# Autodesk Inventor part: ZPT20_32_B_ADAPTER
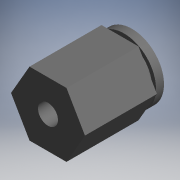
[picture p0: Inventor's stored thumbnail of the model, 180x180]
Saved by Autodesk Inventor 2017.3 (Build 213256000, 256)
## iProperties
Part Number: ZPT20_32_B_ADAPTER
Material: Generic
Catalog Web Link: www.cadenas.de
Description: ZPT_20_32B_ADEPTER-Vacuum Pad/Vertical Vacuum Entry With Buffer
Vendor: SMC
Document SubType Name: Modeling
Designer: partserver
Manufacturer: SMC
Mass: 0.516797 g
Surface Area: 4.92606 cm^2
Volume: 0.516797 cm^3
Density: 1 g/cm^3
Appearance: PSOLRGB-128-128-128
Category: PARTsolutions
Company: SMC
Title: ZPT20_32_B_ADAPTER
Author: Cadenas PARTsolutions
Comments: Vacuum Pad/Vertical Vacuum Entry With Buffer
PSOL_IDENT_0: {$CADENAS_DATA\23d-libs\smc_jp\vacuum_equipment\vacuum_pad\zp\zpt_b\zpt_20_32_b\parts\zpt_20_32_adap
PSOL_IDENT_1: ter_b.prj},188 {VTYP=3D},{NB=ZPT20_32_B_ADAPTER},{LINA=ZPT20_32_B_ADAPTER},{NN=ZPT_20_32B_ADEPTER},{
PSOL_IDENT_2: DATE=03.02.2021 04:15:18},{GEOMDATE=10.02.2011 07:46:00},{VERSION=},{LINEID=10},{WBVAR=},{WBNUMERIC=
PSOL_IDENT_3: }  {NB=ZPT20_32_B_ADAPTER},{LINA=ZPT20_32_B_ADAPTER},{KT=DUMMY},{ORDER=ZPT20_32}
NB: ZPT20_32_B_ADAPTER
NN: ZPT_20_32B_ADEPTER
NT: Vacuum Pad/Vertical Vacuum Entry With Buffer
NBSYN: $ORDER._B_ADAPTER
LINA: ZPT20_32_B_ADAPTER
CATALOG: SMC (JP
ORDER: ZPT20_32
SUPPLIER: SMC
ARTICLENO: ZPT20_32_B_ADAPTER
BOMINFO: ZPT20_32_B_ADAPTER
CREATOR: CADENAS GmbH
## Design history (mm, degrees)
sketch "Sketch_1"
  geometry: L1 (4.619, 0)-(2.309, 4); L2 (2.309, 4)-(-2.309, 4); L3 (-2.309, 4)-(-4.619, 0); L4 (-4.619, 0)-(-2.309, -4); L5 (-2.309, -4)-(2.309, -4); L6 (2.309, -4)-(4.619, 0)
  constraints: 12 end point
extrude "Extrusion1" join sketch "Sketch_1" distance "d0" = 9; taper "d1" = 0 deg
sketch "Sketch_2"
  geometry: L1 (0, 9)-(0, 10.5); L2 (0, 10.5)-(4, 10.5); L3 (4, 10.5)-(4, 9.5); L4 (4, 9.5)-(3.5, 9.5); L5 (3.5, 9.5)-(3.5, 9); L6 (3.5, 9)-(0, 9); L7 (0, 9)-(0, 10.5)
  constraints: 14 end point
revolve "Revolution1" sketch "Sketch_2" stored, may be unused: angle "d2" = 360 deg
sketch "Sketch3"
  geometry: 1 further point
hole "Hole1" sketch "Sketch3" at (0, 0) diameter "d3" = 2.5; stored, may be unused: countersink angle "d7" = 90 deg, drill point angle "d9" = 0 deg; dims "d4" = 6, "d5" = 4, "d6" = 2, "d8" = 10.5
node "adapter_XY"
node "adapter_YZ"
node "adapter_ZX"
node "adapter_X"
node "adapter_Y"
node "adapter_Z"
node "adapter_Center"
node "buffer_XY"
node "buffer_YZ"
node "buffer_ZX"
node "buffer_X"
node "buffer_Y"
node "buffer_Z"
node "buffer_Center"
body "Solid1"
other parameters: "d10" = 0, "d11" = 0
